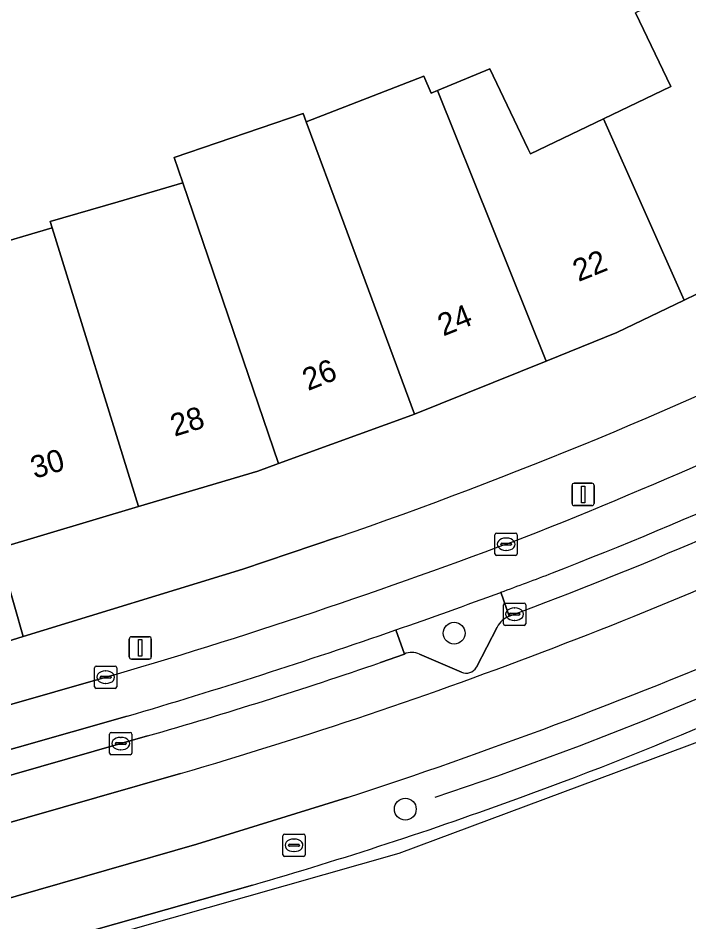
# Model space of a CAD drawing. Extents: x 161798 to 162385, y 382315 to 382833.
# Drawn here: x 162265.82 to 162295.9, y 382494.42 to 382534.95 of the extents above; entities that cross this region are included whole.
import ezdxf

# ---------------------------------------------------------------- set-up
doc = ezdxf.new("R2010")
doc.units = 0
for name, color, linetype in [('IMGEO_Berm_groen', 7, 'Continuous'), ('IMGEO_Berm_open', 7, 'Continuous'), ('IMGEO_Boom', 7, 'Continuous'), ('IMGEO_Erf', 7, 'Continuous'), ('IMGEO_Fietspad_open', 7, 'Continuous'), ('IMGEO_Hek', 7, 'Continuous'), ('IMGEO_Kolk', 7, 'Continuous'), ('IMGEO_Lichtmast', 7, 'Continuous'), ('IMGEO_Pand', 7, 'Continuous'), ('IMGEO_Pand_nummerreeks', 7, 'Continuous'), ('IMGEO_Parkeervlak_open', 7, 'Continuous'), ('IMGEO_Rijbaan_lokaal_gesloten', 7, 'Continuous'), ('IMGEO_Rioolput', 7, 'Continuous'), ('IMGEO_Voetpad_open', 7, 'Continuous')]:
    doc.layers.add(name, color=color, linetype=linetype)

msp = doc.modelspace()

# ---------------------------------------------------------------- linework, layer by layer
at = {"layer": 'IMGEO_Berm_groen'}
for points in [[(162287.838, 382508.126), (162287.464, 382509.2)], [(162282.758, 382507.514), (162283.143, 382506.433)], [(162286.369, 382505.842), (162287.303, 382507.644)], [(162283.82, 382506.423), (162285.696, 382505.621)], [(162280.595, 382500), (162273.843, 382497.909), (162253.573, 382492.078), (162194.344, 382475.272), (162190.754, 382474.253)], [(162196.083, 382473.27), (162254.078, 382489.776), (162276.34, 382496.076)]]:
    msp.add_lwpolyline(points, dxfattribs=at)
for centre, radius, start, end in [((162209.611, 382717.286), 228.587, 288.0915, 298.00122), ((162195.104, 382759.587), 266.879, 289.17427, 290.24749), ((162224.976, 382673.566), 184.772, 290.05685, 296.47061), ((162288.189, 382507.199), 0.991, 110.7212, 153.3124), ((162283.471, 382505.743), 0.764, 62.8559, 115.4516), ((162285.914, 382506.094), 0.52, 245.297, 331.0613), ((162224.576, 382674.751), 186.022, 286.15682, 290.04739)]:
    msp.add_arc(centre, radius, start, end, dxfattribs=at)
at = {"layer": 'IMGEO_Berm_open'}
for points in [[(162287.464, 382509.2), (162287.838, 382508.126)], [(162282.067, 382506.052), (162283.143, 382506.433), (162282.758, 382507.514)], [(162270.708, 382503.646), (162258.268, 382500.103), (162258.568, 382499.022), (162271.629, 382502.762)]]:
    msp.add_lwpolyline(points, dxfattribs=at)
for centre, radius, start, end in [((162206.452, 382722.991), 228.647, 291.37391, 296.44995), ((162212.514, 382708.567), 214.126, 290.59577, 295.64179), ((162181.726, 382794.9), 304.639, 290.30962, 290.77539), ((162196.641, 382755.091), 262.127, 286.41315, 289.17968), ((162212.835, 382707.496), 213.009, 286.0225, 288.96663)]:
    msp.add_arc(centre, radius, start, end, dxfattribs=at)
at = {"layer": 'IMGEO_Boom'}
for centre in [(162285.372, 382507.366), (162283.183, 382499.481)]:
    msp.add_circle(centre, 0.489, dxfattribs=at)
at = {"layer": 'IMGEO_Erf'}
for points in [[(162264.296, 382524.652), (162267.357, 382525.54), (162267.267, 382525.831), (162270.306, 382526.712), (162273.214, 382527.556), (162272.826, 382528.696), (162278.602, 382530.663), (162278.74, 382530.291), (162284.018, 382532.337), (162284.346, 382531.578), (162284.621, 382531.692), (162286.967, 382532.667), (162288.678, 382529.104), (162288.797, 382528.857), (162292.064, 382530.429), (162295.088, 382531.885), (162293.499, 382535.175)], [(162296.236, 382522.566), (162295.69, 382522.304), (162292.661, 382520.85), (162289.496, 382519.571), (162283.602, 382517.19), (162283.472, 382517.138), (162277.501, 382514.97), (162276.575, 382514.634), (162271.221, 382513.041), (162264.914, 382511.164), (162266.056, 382507.22), (162275.901, 382510.235), (162280.146, 382511.67)]]:
    msp.add_lwpolyline(points, dxfattribs=at)
msp.add_arc((162213.266, 382705.461), 205.007, 289.04039, 296.02246, dxfattribs=at)
at = {"layer": 'IMGEO_Fietspad_open'}
for points in [[(162270.134, 382505.503), (162251.815, 382500.25), (162250.936, 382500), (162191.958, 382483.232), (162189.171, 382482.44)], [(162252.125, 382498.353), (162253.443, 382498.728), (162257.907, 382500), (162258.268, 382500.103), (162270.708, 382503.646)]]:
    msp.add_lwpolyline(points, dxfattribs=at)
for centre, radius, start, end in [((162186.757, 382767.203), 275.058, 291.84588, 296.0275), ((162206.452, 382722.991), 228.647, 291.37391, 296.44995), ((162197.697, 382751.821), 256.748, 286.38749, 290.85702), ((162181.726, 382794.9), 304.639, 290.30962, 290.77539), ((162195.104, 382759.587), 266.879, 289.17427, 290.24749), ((162196.641, 382755.091), 262.127, 286.41315, 289.17968)]:
    msp.add_arc(centre, radius, start, end, dxfattribs=at)
at = {"layer": 'IMGEO_Hek'}
msp.add_lwpolyline([(162316.673, 382514.262), (162312.308, 382511.879), (162309.031, 382510.186), (162305.011, 382508.232), (162300.94, 382506.386), (162296.821, 382504.651), (162293.878, 382503.434), (162290.971, 382502.298), (162287.319, 382500.957), (162284.503, 382500)], dxfattribs=at)
at = {"layer": 'IMGEO_Kolk'}
for p, q in [((162287.279, 382511.856), (162288.131, 382511.856)), ((162287.204, 382510.93), (162287.204, 382511.782)), ((162287.506, 382511.399), (162287.904, 382511.399)), ((162287.692, 382511.636), (162287.717, 382511.636)), ((162288.205, 382511.782), (162288.205, 382510.93)), ((162287.463, 382511.35), (162287.463, 382511.362)), ((162287.901, 382511.313), (162287.503, 382511.313)), ((162287.715, 382511.076), (162287.69, 382511.076)), ((162287.947, 382511.362), (162287.947, 382511.35)), ((162288.131, 382510.856), (162287.279, 382510.856)), ((162287.583, 382507.794), (162287.583, 382508.646)), ((162287.658, 382508.72), (162288.51, 382508.72)), ((162288.584, 382508.646), (162288.584, 382507.794)), ((162287.842, 382508.214), (162287.842, 382508.226)), ((162288.28, 382508.177), (162287.882, 382508.177)), ((162287.885, 382508.263), (162288.283, 382508.263)), ((162288.071, 382508.5), (162288.096, 382508.5)), ((162288.326, 382508.226), (162288.326, 382508.214)), ((162288.094, 382507.94), (162288.069, 382507.94)), ((162288.51, 382507.72), (162287.658, 382507.72)), ((162269.249, 382504.968), (162269.249, 382505.82)), ((162269.324, 382505.894), (162270.176, 382505.894)), ((162270.25, 382505.82), (162270.25, 382504.968)), ((162269.508, 382505.388), (162269.508, 382505.4)), ((162269.946, 382505.351), (162269.548, 382505.351)), ((162269.551, 382505.437), (162269.949, 382505.437)), ((162269.737, 382505.674), (162269.762, 382505.674)), ((162269.992, 382505.4), (162269.992, 382505.388)), ((162269.76, 382505.114), (162269.735, 382505.114)), ((162270.176, 382504.894), (162269.324, 382504.894)), ((162270, 382502.919), (162270.852, 382502.919)), ((162269.925, 382501.993), (162269.925, 382502.845)), ((162270.413, 382502.699), (162270.438, 382502.699)), ((162270.926, 382502.845), (162270.926, 382501.993)), ((162270.184, 382502.413), (162270.184, 382502.425)), ((162270.622, 382502.376), (162270.224, 382502.376)), ((162270.227, 382502.462), (162270.625, 382502.462)), ((162270.436, 382502.139), (162270.411, 382502.139)), ((162270.668, 382502.425), (162270.668, 382502.413)), ((162270.852, 382501.919), (162270, 382501.919))]:
    msp.add_line(p, q, dxfattribs=at)
for points in [[(162287.279, 382511.856), (162288.131, 382511.856)], [(162287.204, 382510.93), (162287.204, 382511.782)], [(162288.205, 382511.782), (162288.205, 382510.93)], [(162288.131, 382510.856), (162287.279, 382510.856)], [(162287.583, 382507.794), (162287.583, 382508.646)], [(162287.658, 382508.72), (162288.51, 382508.72)], [(162288.584, 382508.646), (162288.584, 382507.794)], [(162288.51, 382507.72), (162287.658, 382507.72)], [(162269.249, 382504.968), (162269.249, 382505.82)], [(162269.324, 382505.894), (162270.176, 382505.894)], [(162270.25, 382505.82), (162270.25, 382504.968)], [(162270.176, 382504.894), (162269.324, 382504.894)], [(162270, 382502.919), (162270.852, 382502.919)], [(162269.925, 382501.993), (162269.925, 382502.845)], [(162270.926, 382502.845), (162270.926, 382501.993)], [(162270.852, 382501.919), (162270, 382501.919)]]:
    msp.add_lwpolyline(points, dxfattribs=at)
for centre, radius, start, end in [((162287.281, 382511.78), 0.0765, 91.552, 178.448), ((162287.281, 382511.78), 0.0765, 91.552, 178.448), ((162288.129, 382511.78), 0.0765, 1.552, 88.448), ((162288.129, 382511.78), 0.0765, 1.552, 88.448), ((162287.503, 382511.359), 0.0403, 85.8775, 175.7526), ((162287.908, 382511.361), 0.0386, 1.7309, 96.639), ((162287.5, 382511.349), 0.0366, 178.938, 274.7102), ((162287.904, 382511.356), 0.043, 264.8664, 352.4533), ((162287.281, 382510.932), 0.0765, 181.552, 268.448), ((162287.281, 382510.932), 0.0765, 181.552, 268.448), ((162288.129, 382510.932), 0.0765, 271.552, 358.448), ((162288.129, 382510.932), 0.0765, 271.552, 358.448), ((162287.66, 382508.644), 0.0765, 91.552, 178.448), ((162287.66, 382508.644), 0.0765, 91.552, 178.448), ((162288.508, 382508.644), 0.0765, 1.552, 88.448), ((162288.508, 382508.644), 0.0765, 1.552, 88.448), ((162287.882, 382508.223), 0.0403, 85.8775, 175.7526), ((162287.879, 382508.213), 0.0366, 178.938, 274.7102), ((162288.283, 382508.22), 0.043, 264.8664, 352.4533), ((162288.287, 382508.225), 0.0386, 1.7309, 96.639), ((162287.66, 382507.796), 0.0765, 181.552, 268.448), ((162287.66, 382507.796), 0.0765, 181.552, 268.448), ((162288.508, 382507.796), 0.0765, 271.552, 358.448), ((162288.508, 382507.796), 0.0765, 271.552, 358.448), ((162269.326, 382505.818), 0.0765, 91.552, 178.448), ((162269.326, 382505.818), 0.0765, 91.552, 178.448), ((162270.174, 382505.818), 0.0765, 1.552, 88.448), ((162270.174, 382505.818), 0.0765, 1.552, 88.448), ((162269.548, 382505.397), 0.0403, 85.8775, 175.7526), ((162269.545, 382505.387), 0.0366, 178.938, 274.7102), ((162269.949, 382505.394), 0.043, 264.8664, 352.4533), ((162269.953, 382505.399), 0.0386, 1.7309, 96.639), ((162269.326, 382504.97), 0.0765, 181.552, 268.448), ((162269.326, 382504.97), 0.0765, 181.552, 268.448), ((162270.174, 382504.97), 0.0765, 271.552, 358.448), ((162270.174, 382504.97), 0.0765, 271.552, 358.448), ((162270.002, 382502.843), 0.0765, 91.552, 178.448), ((162270.002, 382502.843), 0.0765, 91.552, 178.448), ((162270.85, 382502.843), 0.0765, 1.552, 88.448), ((162270.85, 382502.843), 0.0765, 1.552, 88.448), ((162270.224, 382502.422), 0.0403, 85.8775, 175.7526), ((162270.221, 382502.412), 0.0366, 178.938, 274.7102), ((162270.625, 382502.419), 0.043, 264.8664, 352.4533), ((162270.629, 382502.424), 0.0386, 1.7309, 96.639), ((162270.002, 382501.995), 0.0765, 181.552, 268.448), ((162270.002, 382501.995), 0.0765, 181.552, 268.448), ((162270.85, 382501.995), 0.0765, 271.552, 358.448), ((162270.85, 382501.995), 0.0765, 271.552, 358.448)]:
    msp.add_arc(centre, radius, start, end, dxfattribs=at)
for centre, major_axis, ratio, start_param, end_param in [((162287.691, 382511.356), (-0.387, 0.002), 0.722429, 4.712389, 7.853982), ((162287.716, 382511.356), (-0.39, 0.002), 0.717154, 1.570796, 4.712389), ((162288.07, 382508.22), (-0.387, 0.002), 0.722429, 4.712389, 7.853982), ((162288.095, 382508.22), (-0.39, 0.002), 0.717154, 1.570796, 4.712389), ((162269.736, 382505.394), (-0.387, 0.002), 0.722429, 4.712389, 7.853982), ((162269.761, 382505.394), (-0.39, 0.002), 0.717154, 1.570796, 4.712389), ((162270.412, 382502.419), (-0.387, 0.002), 0.722429, 4.712389, 7.853982), ((162270.437, 382502.419), (-0.39, 0.002), 0.717154, 1.570796, 4.712389)]:
    msp.add_ellipse(centre, major_axis=major_axis, ratio=ratio, start_param=start_param, end_param=end_param, dxfattribs=at)
at = {"layer": 'IMGEO_Lichtmast'}
for p, q in [((162290.657, 382513.188), (162290.657, 382513.988)), ((162290.657, 382513.988), (162290.657, 382513.188)), ((162290.757, 382514.088), (162291.547, 382514.088)), ((162291.547, 382514.088), (162290.757, 382514.088)), ((162291.647, 382513.988), (162291.647, 382513.188)), ((162291.647, 382513.188), (162291.647, 382513.988)), ((162291.547, 382513.088), (162290.757, 382513.088)), ((162290.757, 382513.088), (162291.547, 382513.088)), ((162270.807, 382506.307), (162270.807, 382507.107)), ((162270.807, 382507.107), (162270.807, 382506.307)), ((162270.907, 382507.207), (162271.697, 382507.207)), ((162271.697, 382507.207), (162270.907, 382507.207)), ((162271.797, 382507.107), (162271.797, 382506.307)), ((162271.797, 382506.307), (162271.797, 382507.107)), ((162271.697, 382506.207), (162270.907, 382506.207)), ((162270.907, 382506.207), (162271.697, 382506.207))]:
    msp.add_line(p, q, dxfattribs=at)
for points in [[(162291.077, 382513.963), (162291.227, 382513.963), (162291.227, 382513.213), (162291.077, 382513.213), (162291.077, 382513.963)], [(162271.227, 382507.082), (162271.377, 382507.082), (162271.377, 382506.332), (162271.227, 382506.332), (162271.227, 382507.082)]]:
    msp.add_lwpolyline(points, dxfattribs=at)
for centre, start, end in [((162290.757, 382513.988), 90, 180), ((162290.757, 382513.988), 90, 180), ((162291.547, 382513.988), 0, 90), ((162291.547, 382513.988), 360, 90), ((162290.757, 382513.188), 180, 270), ((162290.757, 382513.188), 180, 270), ((162291.547, 382513.188), 270, 0), ((162291.547, 382513.188), 270, 0), ((162270.907, 382507.107), 90, 180), ((162270.907, 382507.107), 90, 180), ((162271.697, 382507.107), 0, 90), ((162271.697, 382507.107), 360, 90), ((162270.907, 382506.307), 180, 270), ((162270.907, 382506.307), 180, 270), ((162271.697, 382506.307), 270, 0), ((162271.697, 382506.307), 270, 0)]:
    msp.add_arc(centre, 0.1, start, end, dxfattribs=at)
at = {"layer": 'IMGEO_Pand'}
for points in [[(162292.064, 382530.429), (162295.69, 382522.304), (162296.236, 382522.566), (162296.494, 382522.029), (162298.553, 382523.017), (162298.349, 382523.442), (162302.098, 382525.243), (162297.096, 382535.665), (162296.602, 382536.668), (162293.499, 382535.175), (162295.088, 382531.885)], [(162289.496, 382519.571), (162292.661, 382520.85), (162295.69, 382522.304), (162292.064, 382530.429), (162288.797, 382528.857), (162288.678, 382529.104), (162286.967, 382532.667), (162284.621, 382531.692)], [(162284.621, 382531.692), (162284.346, 382531.578), (162284.018, 382532.337), (162278.74, 382530.291), (162280.426, 382525.748), (162283.602, 382517.19), (162289.496, 382519.571)], [(162280.426, 382525.748), (162278.74, 382530.291), (162278.602, 382530.663), (162272.826, 382528.696), (162273.214, 382527.556), (162277.501, 382514.97), (162283.472, 382517.138), (162283.602, 382517.19)], [(162273.214, 382527.556), (162270.306, 382526.712), (162267.267, 382525.831), (162267.357, 382525.54), (162271.221, 382513.041), (162276.575, 382514.634), (162277.501, 382514.97)], [(162267.357, 382525.54), (162264.296, 382524.652), (162261.257, 382523.77), (162262.272, 382520.271), (162264.914, 382511.164), (162271.221, 382513.041)]]:
    msp.add_lwpolyline(points, close=True, dxfattribs=at)
at = {"layer": 'IMGEO_Parkeervlak_open'}
for points in [[(162287.303, 382507.644), (162286.369, 382505.842)], [(162283.143, 382506.433), (162282.067, 382506.052)], [(162285.696, 382505.621), (162283.82, 382506.423)], [(162271.629, 382502.762), (162258.568, 382499.022)], [(162252.312, 382495.11), (162269.349, 382500), (162273.101, 382501.077)]]:
    msp.add_lwpolyline(points, dxfattribs=at)
for centre, radius, start, end in [((162212.514, 382708.567), 214.126, 290.59577, 295.64179), ((162212.975, 382707.284), 214.794, 286.25569, 295.68276), ((162288.189, 382507.199), 0.991, 110.7212, 153.3124), ((162283.471, 382505.743), 0.764, 62.8559, 115.4516), ((162212.835, 382707.496), 213.009, 286.0225, 288.96663), ((162285.914, 382506.094), 0.52, 245.297, 331.0613)]:
    msp.add_arc(centre, radius, start, end, dxfattribs=at)
at = {"layer": 'IMGEO_Rijbaan_lokaal_gesloten'}
for points in [[(162050.268, 382372.421), (162072.514, 382380.58), (162108.457, 382405.716), (162118.152, 382417.002), (162130.306, 382431.424), (162145.022, 382444.832), (162160.813, 382456.745), (162180.588, 382467.067), (162185.966, 382468.979), (162201.279, 382474.422), (162245.387, 382486.842), (162282.905, 382497.501), (162306.448, 382506.279), (162315.724, 382511.35)], [(162273.101, 382501.077), (162269.349, 382500), (162252.312, 382495.11), (162193.433, 382478.31), (162190.53, 382477.482)], [(162273.843, 382497.909), (162280.595, 382500)], [(162190.754, 382474.253), (162194.344, 382475.272), (162253.573, 382492.078), (162273.843, 382497.909)], [(162276.34, 382496.076), (162254.078, 382489.776), (162196.083, 382473.27)]]:
    msp.add_lwpolyline(points, dxfattribs=at)
for centre, radius, start, end in [((162209.611, 382717.286), 228.587, 288.0915, 298.00122), ((162212.975, 382707.284), 214.794, 286.25569, 295.68276), ((162224.976, 382673.566), 184.772, 290.05685, 296.47061), ((162224.576, 382674.751), 186.022, 286.15682, 290.04739)]:
    msp.add_arc(centre, radius, start, end, dxfattribs=at)
at = {"layer": 'IMGEO_Rioolput'}
for p, q in [((162277.693, 382497.433), (162277.693, 382498.285)), ((162277.768, 382498.359), (162278.62, 382498.359)), ((162278.181, 382498.139), (162278.206, 382498.139)), ((162278.694, 382498.285), (162278.694, 382497.433)), ((162277.952, 382497.853), (162277.952, 382497.865)), ((162278.39, 382497.816), (162277.992, 382497.816)), ((162277.995, 382497.902), (162278.393, 382497.902)), ((162278.436, 382497.865), (162278.436, 382497.853)), ((162278.62, 382497.359), (162277.768, 382497.359)), ((162278.204, 382497.579), (162278.179, 382497.579))]:
    msp.add_line(p, q, dxfattribs=at)
for points in [[(162277.693, 382497.433), (162277.693, 382498.285)], [(162277.768, 382498.359), (162278.62, 382498.359)], [(162278.694, 382498.285), (162278.694, 382497.433)], [(162278.62, 382497.359), (162277.768, 382497.359)]]:
    msp.add_lwpolyline(points, dxfattribs=at)
for centre, radius, start, end in [((162277.77, 382498.283), 0.0765, 91.552, 178.448), ((162277.77, 382498.283), 0.0765, 91.552, 178.448), ((162278.618, 382498.283), 0.0765, 1.552, 88.448), ((162278.618, 382498.283), 0.0765, 1.552, 88.448), ((162277.992, 382497.862), 0.0403, 85.8775, 175.7526), ((162277.989, 382497.852), 0.0366, 178.938, 274.7102), ((162278.393, 382497.859), 0.043, 264.8664, 352.4533), ((162278.397, 382497.864), 0.0386, 1.7309, 96.639), ((162277.77, 382497.435), 0.0765, 181.552, 268.448), ((162277.77, 382497.435), 0.0765, 181.552, 268.448), ((162278.618, 382497.435), 0.0765, 271.552, 358.448), ((162278.618, 382497.435), 0.0765, 271.552, 358.448)]:
    msp.add_arc(centre, radius, start, end, dxfattribs=at)
for centre, major_axis, ratio, start_param, end_param in [((162278.18, 382497.859), (-0.387, 0.002), 0.722429, 4.712389, 7.853982), ((162278.205, 382497.859), (-0.39, 0.002), 0.717154, 1.570796, 4.712389)]:
    msp.add_ellipse(centre, major_axis=major_axis, ratio=ratio, start_param=start_param, end_param=end_param, dxfattribs=at)
at = {"layer": 'IMGEO_Voetpad_open'}
for points in [[(162280.146, 382511.67), (162275.901, 382510.235), (162266.056, 382507.22), (162265.144, 382506.94), (162262.221, 382506.045), (162240.584, 382500), (162187.464, 382484.653), (162179.692, 382482.178), (162170.756, 382478.827)], [(162265.144, 382506.94), (162266.056, 382507.22), (162264.914, 382511.164)], [(162250.936, 382500), (162251.815, 382500.25), (162270.134, 382505.503)]]:
    msp.add_lwpolyline(points, dxfattribs=at)
for centre, radius, start, end in [((162213.266, 382705.461), 205.007, 289.04039, 296.02246), ((162186.757, 382767.203), 275.058, 291.84588, 296.0275), ((162197.697, 382751.821), 256.748, 286.38749, 290.85702)]:
    msp.add_arc(centre, radius, start, end, dxfattribs=at)

# ---------------------------------------------------------------- texts
at = {"layer": 'IMGEO_Pand_nummerreeks'}
for s, rotation, p in [('22', 21.959, (162290.947, 382523.108)), ('24', 21.9615, (162284.887, 382520.666)), ('26', 21.9615, (162278.824, 382518.221)), ('28', 17.0752, (162272.837, 382516.174)), ('30', 16.5757, (162266.562, 382514.284))]:
    msp.add_text(s, height=1, rotation=rotation, dxfattribs=at).set_placement(p)

doc.saveas('drawing.dxf')
